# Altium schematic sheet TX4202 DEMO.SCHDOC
size A; SheetNumber: 0; SheetTotal: 0
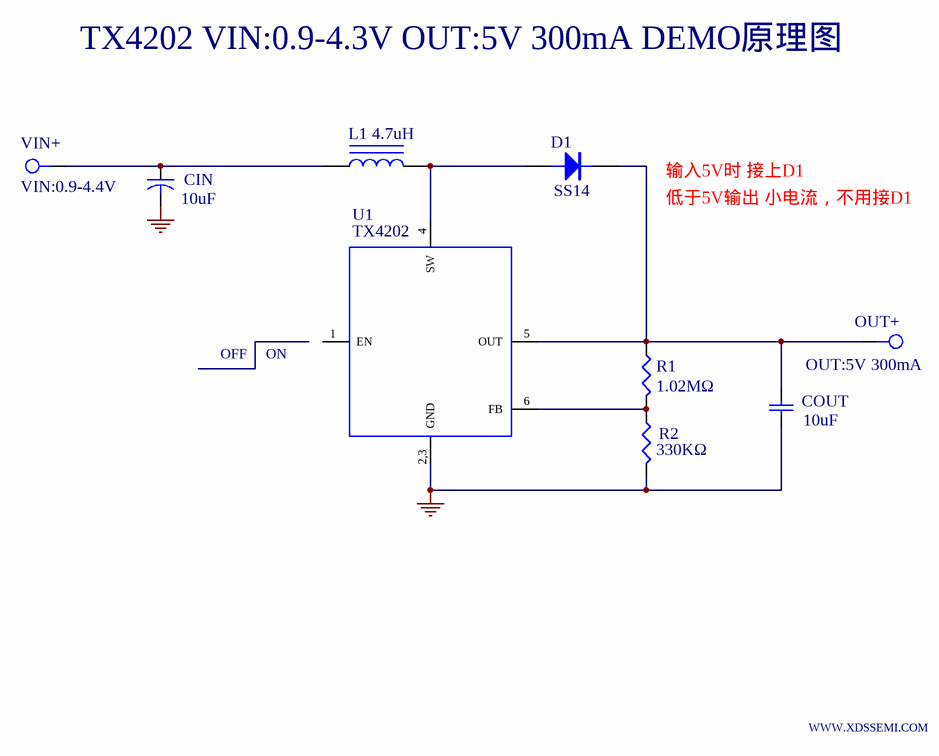
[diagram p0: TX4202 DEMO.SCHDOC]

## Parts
CIN  10uF  [C10*16]
COUT  10uF  [R0805]
D1  SS14
L1_4.7uH  (no value)  [L10*16]
OUT+  OUT:5V 300mA  [P]
R1  1.02MΩ  [R1206]
R2  330KΩ  [R1206]
U1  TX4202
VIN+  VIN:0.9-4.4V  [P]

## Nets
GND: CIN.2 COUT.2 R2.2 U1.2,3(GND)
NetCIN_1: CIN.1 L1_4.7uH.1 VIN+.P
NetCOUT_1: COUT.1 D1.2(K) OUT+.P R1.1 U1.5(OUT)
NetD1_1: D1.1(A) L1_4.7uH.2 U1.4(SW)
NetR1_2: R1.2 R2.1 U1.6(FB)

Not connected (* = marked no-connect by the designer): U1 1(EN)

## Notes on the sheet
- TX4202 VIN:0.9-4.3V OUT:5V 300mA DEMO原理图
- 输入5V时 接上D1
- 低于5V输出 小电流，不用接D1
- OFF
- ON
- WWW.XDSSEMI.COM

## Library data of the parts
CIN = CAPACITOR
COUT = CAP: Capacitor
D1 = DIODE
L1_4.7uH = INDUCTOR IRON
OUT+ VIN+ = P
R1 R2 = RES1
